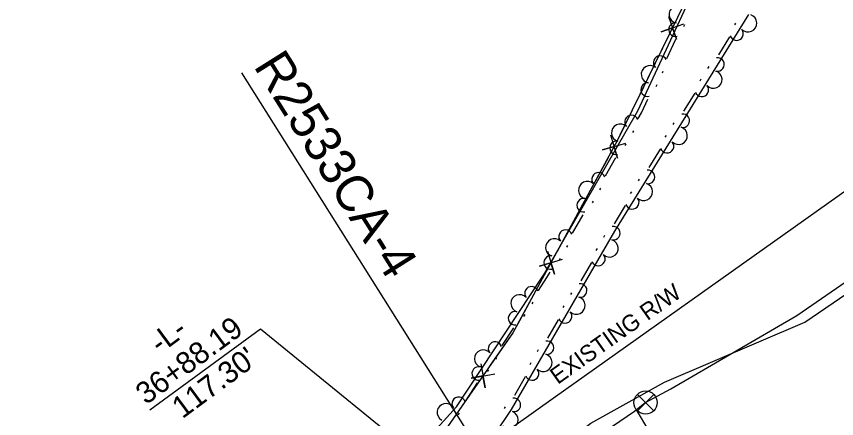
# Model space of a CAD drawing. Extents: x 1577032 to 1581865, y 611492 to 615011.
# Drawn here: x 1580247.3 to 1580404.9, y 613790 to 613867.3 of the extents above; entities that cross this region are included whole.
import ezdxf

# ---------------------------------------------------------------- set-up
doc = ezdxf.new("R2010")
doc.units = 0
for name, color, linetype in [('Exist Horizontal Baseline Alignment Station Label', 7, 'Continuous'), ('Exist Right of Way Line', 7, 'Continuous'), ('Exist Right of Way Line Text', 7, 'Continuous'), ('Exist Right of Way Monument Leader', 7, 'Continuous'), ('Exist Right of Way Monument Text', 7, 'Continuous'), ('Exist Utilities Telephone UG FO SUE LOS B', 7, 'Continuous'), ('Exist Utilities Water UG Line SUE LOS B', 7, 'Continuous'), ('Exist Utilities Water Valve CELL', 7, 'Continuous'), ('Old_Level_11', 7, 'Continuous'), ('Old_Level_8', 7, 'Continuous')]:
    doc.layers.add(name, color=color, linetype=linetype)

msp = doc.modelspace()

# ---------------------------------------------------------------- linework, layer by layer
at = {"layer": 'Exist Horizontal Baseline Alignment Station Label'}
msp.add_line((1580377.72, 613717.98), (1580290.63, 613856.46), dxfattribs=at)
at = {"layer": 'Exist Right of Way Line'}
for points in [[(1580350.49, 613793.9), (1581560.23, 614652.99)], [(1580329.14, 613778.75), (1580350.49, 613793.9)]]:
    msp.add_lwpolyline(points, dxfattribs=at)
at = {"layer": 'Exist Right of Way Monument Leader'}
msp.add_lwpolyline([(1580329.14, 613778.75), (1580294.18, 613807.2), (1580272.94, 613791.61)], dxfattribs=at)
at = {"layer": 'Exist Utilities Telephone UG FO SUE LOS B'}
msp.add_lwpolyline([(1579762.43, 613445.5), (1579805.52, 613477.49), (1579874.3, 613528.42), (1579927.63, 613567.61), (1579961.57, 613589.13), (1580023.79, 613630.1), (1580048.6, 613644.24), (1580064.79, 613652.02), (1580101.01, 613664.86), (1580134.79, 613676.2), (1580157.3, 613683.34), (1580171.65, 613687.07), (1580205.63, 613699.27), (1580257.8, 613718.78), (1580277.93, 613732.3), (1580322.48, 613762.42), (1580357.71, 613789.14), (1580371.84, 613797.02), (1580398.85, 613808.57), (1580440.4, 613836.96), (1580497.32, 613877.42), (1580541.92, 613911.34), (1580565.99, 613928.5)], dxfattribs=at)
at = {"layer": 'Exist Utilities Water UG Line SUE LOS B'}
for p, q in [((1580397.3, 613809.79), (1580439.29, 613838.87)), ((1580373.09, 613795.75), (1580397.3, 613809.79)), ((1580368.11, 613793.02), (1580373.09, 613795.75)), ((1580366.07, 613791.44), (1580368.11, 613793.02)), ((1580358.85, 613786.52), (1580366.07, 613791.44)), ((1580368.83, 613787.68), (1580366.46, 613791.68))]:
    msp.add_line(p, q, dxfattribs=at)
at = {"layer": 'Exist Utilities Water Valve CELL'}
msp.add_lwpolyline([(1580369.79, 613794.65), (1580366.64, 613791.5), (1580368.22, 613793.08), (1580369.79, 613791.5), (1580366.64, 613794.65)], dxfattribs=at)
msp.add_circle((1580368.22, 613793.08), 2.23, dxfattribs=at)
at = {"layer": 'Old_Level_11'}
for points in [[(1580178.64, 613668.86), (1580237.64, 613712.65), (1580275.25, 613740.08), (1580305.41, 613763.08), (1580331.9, 613792.25), (1580348.57, 613817.56), (1580366.72, 613849.16), (1580382.81, 613883.89)], [(1580387.98, 613867.68), (1580362.26, 613826.06), (1580342.4, 613791.75), (1580326.53, 613768.18), (1580306.87, 613751.68), (1580263.54, 613718.08), (1580232.15, 613692.42), (1580196.05, 613660.28)], [(1580375.6, 613865.39), (1580375.77, 613865.76)], [(1580385.53, 613866.07), (1580385.32, 613865.72)], [(1580384.37, 613863.41), (1580382.22, 613859.92)], [(1580372.29, 613859.24), (1580374.02, 613862.96)], [(1580380.36, 613857.69), (1580380.14, 613857.34)], [(1580371.46, 613856.46), (1580371.63, 613856.83)], [(1580370.25, 613853.85), (1580370.42, 613854.23)], [(1580378.85, 613855.25), (1580378.63, 613854.9)], [(1580377.69, 613852.59), (1580375.53, 613849.1)], [(1580366.82, 613847.69), (1580367.45, 613848.78), (1580368.67, 613851.42)], [(1580373.68, 613846.88), (1580373.46, 613846.53)], [(1580365.75, 613844.99), (1580365.95, 613845.35)], [(1580372.17, 613844.43), (1580371.95, 613844.09)], [(1580364.32, 613842.5), (1580364.52, 613842.86)], [(1580371.01, 613841.78), (1580368.85, 613838.29)], [(1580360.49, 613836.66), (1580362.53, 613840.22)], [(1580366.99, 613836.06), (1580366.78, 613835.71)], [(1580359.42, 613833.97), (1580359.62, 613834.33)], [(1580365.49, 613833.62), (1580365.27, 613833.27)], [(1580357.99, 613831.48), (1580358.19, 613831.84)], [(1580364.33, 613830.96), (1580362.17, 613827.47)], [(1580354.16, 613825.64), (1580356.2, 613829.19)], [(1580360.34, 613825.19), (1580360.13, 613824.83)], [(1580353.08, 613822.94), (1580353.29, 613823.3)], [(1580358.9, 613822.71), (1580358.69, 613822.35)], [(1580351.65, 613820.46), (1580351.86, 613820.81)], [(1580357.82, 613820.01), (1580355.76, 613816.47)], [(1580347.65, 613814.66), (1580349.27, 613817.13), (1580349.87, 613818.17)], [(1580353.97, 613814.19), (1580353.76, 613813.83)], [(1580346.41, 613812.04), (1580346.64, 613812.38)], [(1580352.53, 613811.7), (1580352.32, 613811.35)], [(1580344.83, 613809.64), (1580345.06, 613809.99)], [(1580351.45, 613809.01), (1580349.39, 613805.46)], [(1580340.65, 613804.05), (1580342.91, 613807.47)], [(1580347.6, 613803.19), (1580347.39, 613802.83)], [(1580339.42, 613801.42), (1580339.64, 613801.77)], [(1580346.16, 613800.7), (1580345.95, 613800.35)], [(1580337.84, 613799.03), (1580338.06, 613799.37)], [(1580345.08, 613798.01), (1580343.02, 613794.46)], [(1580333.66, 613793.43), (1580335.92, 613796.85)], [(1580332.2, 613790.74), (1580332.47, 613791.05)], [(1580341.26, 613792.26), (1580341.03, 613791.92)]]:
    msp.add_lwpolyline(points, dxfattribs=at)
for centre, radius, start, end in [((1580374.43, 613867.74), 1.69, 51.1064, 259.1789), ((1580387.92, 613866.03), 1.69, 224.2569, 72.3294), ((1580373.96, 613864.79), 1.3, 83.5776, 284.3742), ((1580385.72, 613864.02), 1.3, 199.0617, 39.8582), ((1580371.03, 613858.46), 1.3, 25.9111, 226.7077), ((1580382.05, 613858.09), 1.3, 256.7281, 97.5247), ((1580369.08, 613856.2), 1.69, 51.1064, 259.1789), ((1580381.24, 613855.22), 1.69, 224.2569, 72.3294), ((1580368.62, 613853.26), 1.3, 83.5776, 284.3742), ((1580379.03, 613853.21), 1.3, 199.0617, 39.8582), ((1580365.5, 613847.03), 1.3, 20.8969, 221.6935), ((1580375.37, 613847.28), 1.3, 256.7281, 97.5247), ((1580363.36, 613844.95), 1.69, 46.0922, 254.1647), ((1580374.56, 613844.4), 1.69, 224.2569, 72.3294), ((1580362.64, 613842.05), 1.3, 78.5634, 279.36), ((1580372.35, 613842.39), 1.3, 199.0617, 39.8582), ((1580359.17, 613836), 1.3, 20.8969, 221.6935), ((1580368.69, 613836.46), 1.3, 256.7281, 97.5247), ((1580357.02, 613833.92), 1.69, 46.0922, 254.1647), ((1580367.88, 613833.59), 1.69, 224.2569, 72.3294), ((1580356.31, 613831.03), 1.3, 78.5634, 279.36), ((1580365.67, 613831.58), 1.3, 199.0617, 39.8582), ((1580352.83, 613824.98), 1.3, 20.8969, 221.6935), ((1580362.02, 613825.64), 1.3, 258.3647, 99.1613), ((1580350.69, 613822.9), 1.69, 46.0922, 254.1647), ((1580361.29, 613822.74), 1.69, 225.8936, 73.966), ((1580349.97, 613820), 1.3, 78.5634, 279.36), ((1580359.14, 613820.67), 1.3, 200.6983, 41.4948), ((1580346.29, 613814.09), 1.3, 17.3993, 218.1958), ((1580355.65, 613814.64), 1.3, 258.3647, 99.1613), ((1580344.02, 613812.14), 1.69, 42.5945, 250.667), ((1580354.92, 613811.74), 1.69, 225.8936, 73.966), ((1580343.13, 613809.29), 1.3, 75.0657, 275.8623), ((1580352.77, 613809.67), 1.3, 200.6983, 41.4948), ((1580339.29, 613803.47), 1.3, 17.3993, 218.1958), ((1580349.28, 613803.63), 1.3, 258.3647, 99.1613), ((1580337.03, 613801.52), 1.69, 42.5945, 250.667), ((1580348.55, 613800.74), 1.69, 225.8936, 73.966), ((1580336.14, 613798.68), 1.3, 75.0657, 275.8623), ((1580346.4, 613798.66), 1.3, 200.6983, 41.4948), ((1580332.3, 613792.85), 1.3, 17.3993, 218.1958), ((1580342.91, 613792.63), 1.3, 258.3647, 99.1613), ((1580329.85, 613791.21), 1.69, 33.7223, 241.7948), ((1580342.04, 613789.75), 1.69, 222.0191, 70.0916)]:
    msp.add_arc(centre, radius, start, end, dxfattribs=at)
at = {"layer": 'Old_Level_8'}
for points in [[(1580540.63, 614164.5), (1580513.16, 614122.65), (1580475.1, 614052.5), (1580441.06, 613980.77), (1580418.75, 613941.93), (1580394.61, 613900.96), (1580375.84, 613870.11), (1580362.75, 613843.38), (1580342.72, 613806.51), (1580317.73, 613770.5), (1580296.57, 613748.74), (1580251.9, 613712.92)], [(1580372.65, 613867.33), (1580374.15, 613862.94), (1580373.4, 613865.14), (1580371.21, 613864.39), (1580375.6, 613865.89)], [(1580372.32, 613862.93), (1580367.81, 613853.72)], [(1580367.81, 613853.72), (1580363.3, 613844.51)], [(1580361.51, 613844.55), (1580362.83, 613840.1), (1580362.17, 613842.33), (1580359.95, 613841.67), (1580364.4, 613842.99)], [(1580361, 613840.17), (1580356.11, 613831.16)], [(1580356.11, 613831.16), (1580351.21, 613822.15)], [(1580349.38, 613822.21), (1580350.7, 613817.76), (1580350.04, 613819.98), (1580347.81, 613819.33), (1580352.26, 613820.64)], [(1580348.86, 613817.82), (1580343.97, 613808.81)], [(1580343.97, 613808.81), (1580342.72, 613806.51), (1580338.37, 613800.24)], [(1580336.55, 613800.5), (1580337.38, 613795.93), (1580336.96, 613798.22), (1580334.68, 613797.8), (1580339.25, 613798.63)], [(1580335.56, 613796.2), (1580329.72, 613787.77)]]:
    msp.add_lwpolyline(points, dxfattribs=at)

# ---------------------------------------------------------------- texts
at = {"layer": 'Exist Horizontal Baseline Alignment Station Label'}
msp.add_text('R2533CA-4', height=7, rotation=302.1645, dxfattribs=at).set_placement((1580292.75, 613857.79))
at = {"layer": 'Exist Right of Way Line Text'}
msp.add_text('EXISTING R/W', height=3.2, rotation=35.38, dxfattribs=at).set_placement((1580351.33, 613796.47))
at = {"layer": 'Exist Right of Way Monument Text'}
for s, p in [('36+88.19', (1580272.2, 613792.53)), ('-L-', (1580274.87, 613802.33)), ("117.30'", (1580279.18, 613789.86))]:
    msp.add_text(s, height=4.2, rotation=36.4288, dxfattribs=at).set_placement(p)

doc.saveas('drawing.dxf')
